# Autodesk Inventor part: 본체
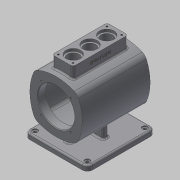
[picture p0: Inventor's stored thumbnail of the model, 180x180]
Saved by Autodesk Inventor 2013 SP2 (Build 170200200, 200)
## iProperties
Created: 2015-11
Part Number: 본체
Material: 일반
Document SubType Name: Modeling
Designer: mduedu
Density: 1 g/cm^3
Author: mduedu
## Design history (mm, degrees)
sketch "스케치2"
  geometry: L1 (0, 250)-(0, -250); L2 (250, 0)-(-250, 0); L3 (-50, 50)-(50, 50); L4 (50, 50)-(50, -50); L5 (50, -50)-(-50, -50); L6 (-50, -50)-(-50, 50); A1 r 90 centre (-40, 0) between (40.415, -40.415) and (40.415, 40.415); A2 r 90 centre (40, 0) between (-40.415, 40.415) and (-40.415, -40.415); A3 r 90 centre (0, -40) between (40.415, 40.415) and (-40.415, 40.415); A4 r 90 centre (0, 40) between (-40.415, -40.415) and (40.415, -40.415); 2 further points
  constraints: 12 end point, 8 point on circle, 4 centre point, 4 tangent, 3 perpendicular, 2 horizontal alignment, 2 midpoint, 2 parallel, 2 symmetric about line, 1 coincident, 1 equal radius, 1 horizontal, 1 vertical, 1 vertical alignment, 2 other
  dimensions: "d6" = 500 distance of L1.start L1.end; "d8" = 500 distance of L2.start L2.end; "d9" = 100 distance of L3.end L4.end; "d11" = 90 radius of A3
extrude "돌출1" new body sketch "스케치2" stored distance "d12" = 130; taper "d13" = 0 deg
fillet "모깎기6" dims "d30" = 15
feature "쉘1" dims "d31" = 15, "d32" = 6, "d33" = 15
sketch "스케치5"
  geometry: C1 r 35 at (0, 0); 1 further point
  constraints: 1 centre point, 1 coincident
  dimensions: "d34" = 70 diameter of C1
extrude "돌출3" cut sketch "스케치5" stored distance "d36" = 3; taper "d37" = 0 deg
node "작업 평면1"
sketch "스케치6"
  geometry: L1 (-65, -60)-(65, -60); L2 (65, -60)-(65, 60); L3 (65, 60)-(-65, 60); L4 (-65, 60)-(-65, -60); L5 (-65, -60)-(65, 60); L6 (65, -60)-(-65, 60); 1 further point
  constraints: 12 end point, 2 midpoint, 2 parallel, 1 horizontal, 1 perpendicular
  dimensions: "d41" = 120 distance of L3.end L1.start; "d43" = 130 distance of L2.end L3.end
extrude "돌출4" join sketch "스케치6" distance "d44" = 10; taper "d45" = 0 deg
sketch "스케치8"
  geometry: L1 (-60, -70)-(60, -70) reference; L2 (0, -50)-(0, -70); L3 (-30, -44.853)-(-30, -70); L4 (30, -44.853)-(30, -70); L5 (-30, -70)-(30, -70); A1 r 90 centre (0, 40) between (-34.941, -42.941) and (34.941, -42.941) reference; A2 r 90 centre (0, 40) between (-30, -44.853) and (30, -44.853); 1 further point
  constraints: 8 end point, 5 point on circle, 2 perpendicular, 2 symmetric about line, 1 centre point, 1 midpoint, 1 point on line
  dimensions: "d48" = 60 distance between parallel lines of L4 L3
extrude "돌출5" join sketch "스케치8" stored distance "d50" = 10; taper "d51" = 0 deg
sketch "스케치17"
  geometry: L1 (65, -50)-(-65, -50) reference; L2 (-65, -70)-(65, -70) reference; L3 (37.721, -50)-(45, -70); L4 (65, -80)-(65, -70) reference; 1 further point
  constraints: 2 end point, 2 point on line
  dimensions: "d128" = 20 distance from line of L3.end L4; "d129" = 110 deg angle of L3 L2
feature "리브1" sketch "스케치17" dims "d130" = 1, "d131" = 10, "d132" = 0, "d133" = 0, "d134" = 1, "d135" = 1
fillet "모깎기17" dims "d136" = 3
fillet "모깎기18" dims "d137" = 3
fillet "모깎기14" dims "d78" = 3
sketch "스케치12"
  geometry: L1 (0, 0)-(28.284, 28.284); L2 (0, 0)-(40, 0); A1 r 40 centre (0, 0) between (28.284, 28.284) and (40, 0); 2 further points
  constraints: 4 end point, 2 coincident, 2 point on circle, 1 centre point, 1 horizontal
  dimensions: "d79" = 80 diameter of A1; "d80" = 45 deg angle of L2 L1
hole "구멍2" sketch "스케치12" at (28.284, 28.284) diameter "d82" = 3.242; stored, may be unused: countersink angle "d86" = 90 deg, drill point angle "d88" = 118 deg; dims "d83" = 9, "d84" = 10, "d85" = 2, "d87" = 11
node "작업 평면2"
sketch "스케치13"
  geometry: L1 (-52.5, -20)-(52.5, -20); L2 (52.5, -20)-(52.5, 20); L3 (52.5, 20)-(-52.5, 20); L4 (-52.5, 20)-(-52.5, -20); L5 (-52.5, -20)-(52.5, 20); L6 (52.5, -20)-(-52.5, 20); 1 further point
  constraints: 12 end point, 2 midpoint, 2 parallel, 1 horizontal, 1 perpendicular
  dimensions: "d93" = 105 distance of L2.end L3.end; "d95" = 40 distance of L1.end L2.end
extrude "돌출8" join sketch "스케치13" stored distance "d96" = 80; taper "d97" = 0 deg
fillet "모깎기15" dims "d98" = 5
fillet "모깎기16" dims "d99" = 3
sketch "스케치14"
  geometry: L1 (-52.5, 15)-(-52.5, -15) reference; L2 (52.5, -15)-(52.5, 15) reference; L3 (-52.5, 0)-(52.5, 0); 4 further points
  constraints: 2 end point, 2 midpoint, 2 point on line, 1 coincident
  dimensions: "d100" = 32 distance of point (-32, 0) point (0, 0); "d102" = 32 distance of point (32, 0) point (0, 0) (derived)
hole "구멍3" sketch "스케치14" at (-32, 0), (0, 0), (32, 0) diameter "d103" = 22; stored, may be unused: countersink angle "d107" = 90 deg, drill point angle "d109" = 118 deg; dims "d104" = 8, "d105" = 28, "d106" = 5, "d108" = 10
sketch "스케치15"
  geometry: L1 (46.5, -14)-(-46.5, -14); L2 (-46.5, -14)-(-46.5, 14); L3 (-46.5, 14)-(46.5, 14); L4 (46.5, 14)-(46.5, -14); L5 (46.5, -14)-(-46.5, 14); L6 (-46.5, -14)-(46.5, 14); L7 (47.5, 20)-(-47.5, 20) reference; L8 (-52.5, 15)-(-52.5, -15) reference; 5 further points
  constraints: 12 end point, 4 coincident, 2 midpoint, 2 parallel, 1 horizontal, 1 perpendicular
  dimensions: "d110" = 6 distance between parallel lines of L3 L7; "d111" = 6 distance between parallel lines of L2 L8
hole "구멍4" sketch "스케치15" at (-46.5, 14), (46.5, 14), (46.5, -14), (-46.5, -14) diameter "d112" = 3.242; stored, may be unused: countersink angle "d116" = 90 deg, drill point angle "d118" = 118 deg; dims "d113" = 10, "d114" = 28, "d115" = 5, "d117" = 13
sketch "스케치16"
  geometry: L1 (33.5, 0)-(61.5, 0) reference; L2 (47.5, 0)-(47.5, -150); L3 (112.5, -150)-(-17.5, -150) reference; 1 further point
  constraints: 2 end point, 2 midpoint, 1 point on line, 1 other
  dimensions: "d122" = 11 distance from line of point (47.5, -11) L1
feature "엠보싱2" sketch "스케치16" dims "d34" = 70, "d123" = 0.5, "d124" = 0
chamfer "모따기1" distance "d125" = 1; stored, may be unused: second distance "d126" = 2, angle "d127" = 45 deg
fillet "모깎기19" dims "d138" = 10
sketch "스케치18"
  geometry: L1 (65, -50)-(65, 50) reference; L2 (-55, -60)-(55, -60) reference; L3 (-65, 50)-(-65, -50) reference; L4 (55, 60)-(-55, 60) reference; A1 r 10 centre (55, 50) between (65, 50) and (55, 60) reference; A2 r 10 centre (55, -50) between (55, -60) and (65, -50) reference; A3 r 10 centre (-55, -50) between (-65, -50) and (-55, -60) reference; A4 r 10 centre (-55, 50) between (-55, 60) and (-65, 50) reference; 5 further points
  constraints: 4 coincident
hole "구멍5" sketch "스케치18" at (-55, 50), (55, 50), (55, -50), (-55, -50) diameter "d139" = 6; stored, may be unused: countersink angle "d143" = 90 deg, drill point angle "d145" = 118 deg; dims "d140" = 6, "d141" = 10, "d142" = 2, "d144" = 8
fillet "모깎기20" dims "d146" = 3
node "솔리드1"
mirror "대칭4"
pattern_circular "원형 패턴1" dims angle "d90" = 360 deg
mirror "대칭3"
node "투영된 루프1"
